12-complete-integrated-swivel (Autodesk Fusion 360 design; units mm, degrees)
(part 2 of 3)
sketch "B Facet 180 Triangle 3" plane through (0, -75, 0) normal (0, -1, 0) x axis (-1, 0, 0)
  line L1 (60.9665, 27.066) -> (-2.067, -27.066)
  line L2 (124, -27.066) -> (60.9665, 27.066)
  line L3 (-2.067, -27.066) -> (124, -27.066)
  line L4 (60.9665, 21.7934) -> (8.7304, -23.066)
  line L5 (113.2026, -23.066) -> (60.9665, 21.7934)
  line L6 (8.7304, -23.066) -> (113.2026, -23.066)
  point P1 (0, 0)
  point P2 (-2.067, -27.066)
  point P3 (60.9665, 27.066)
  point P4 (124, -27.066)
  dimension "d477" distance P1 P2 = 2.067 (= "Linear Dimension-2")
  dimension "d478" distance P1 P2 = 27.066 (= "Linear Dimension-3")
  dimension "d479" distance P1 P3 = 60.9665 (= "Linear Dimension-4")
  dimension "d480" distance P1 P3 = 27.066 (= "Linear Dimension-5")
  dimension "d481" distance P1 P4 = 124 (= "Linear Dimension-6")
  dimension "d482" distance P1 P4 = 27.066 (= "Linear Dimension-7")
  dimension "d483" = 4 (= "memberWidth / 2")
extrude "Extrude14" cut sketch "B Facet 180 Triangle 3" profile of L5 L6 L4 against normal blind 4.7 (magnitude of "-( wall + 0.2 mm )")
sketch "B Facet 180 Triangle 4" plane through (0, -75, 0) normal (0, -1, 0) x axis (-1, 0, 0)
  line L1 (124, -27.066) -> (60.9665, 27.066)
  line L2 (124, 27.066) -> (124, -27.066)
  line L3 (60.9665, 27.066) -> (124, 27.066)
  line L4 (120, -18.3583) -> (71.7639, 23.066)
  line L5 (120, 23.066) -> (120, -18.3583)
  line L6 (71.7639, 23.066) -> (120, 23.066)
  point P1 (0, 0)
  point P2 (60.9665, 27.066)
  point P3 (124, -27.066)
  point P4 (124, 27.066)
  dimension "d486" distance P1 P2 = 60.9665 (= "Linear Dimension-2")
  dimension "d487" distance P1 P2 = 27.066 (= "Linear Dimension-3")
  dimension "d488" distance P1 P3 = 124 (= "Linear Dimension-4")
  dimension "d489" distance P1 P3 = 27.066 (= "Linear Dimension-5")
  dimension "d490" distance P1 P4 = 124 (= "Linear Dimension-6")
  dimension "d491" distance P1 P4 = 27.066 (= "Linear Dimension-7")
  dimension "d492" = -4 (= "-memberWidth / 2")
extrude "Extrude15" cut sketch "B Facet 180 Triangle 4" profile of L5 L6 L4 against normal blind 4.7 (magnitude of "-( wall + 0.2 mm )")
fillet "Fillet5" radius 1.5 (= "apertureRadius")
work_plane "WorkPlane11" RotateAngle 135 ExtraOffset 0
work_plane "WorkPlane12" AlongDistance 75 (= "bodyWidth / 2") ExtraOffset 0
sketch "B Facet 225 Triangle 1" plane through (0, -53.033, -53.033) normal (0, -0.7071, -0.7071) x axis (1, 0, 0)
  line L1 (23.9949, -27.066) -> (62.2721, 27.066)
  line L2 (0.1814, 27.066) -> (23.9949, -27.066)
  line L3 (62.2721, 27.066) -> (0.1814, 27.066)
  line L4 (24.81, -18.9852) -> (54.5447, 23.066)
  line L5 (6.311, 23.066) -> (24.81, -18.9852)
  line L6 (54.5447, 23.066) -> (6.311, 23.066)
  point P1 (0, 0)
  point P2 (62.2721, 27.066)
  point P3 (23.9949, -27.066)
  point P4 (0.1814, 27.066)
  dimension "d501" distance P1 P2 = 62.2721 (= "Linear Dimension-2")
  dimension "d502" distance P1 P2 = 27.066 (= "Linear Dimension-3")
  dimension "d503" distance P1 P3 = 23.9949 (= "Linear Dimension-4")
  dimension "d504" distance P1 P3 = 27.066 (= "Linear Dimension-5")
  dimension "d505" distance P1 P4 = 0.1814 (= "Linear Dimension-6")
  dimension "d506" distance P1 P4 = 27.066 (= "Linear Dimension-7")
  dimension "d507" = 4 (= "memberWidth / 2")
extrude "Extrude16" cut sketch "B Facet 225 Triangle 1" profile of L5 L6 L4 against normal blind 4.7 (magnitude of "-( wall + 0.2 mm )")
sketch "B Facet 225 Triangle 2" plane through (0, -53.033, -53.033) normal (0, -0.7071, -0.7071) x axis (1, 0, 0)
  line L1 (0.1814, 27.066) -> (23.9949, -27.066)
  line L2 (-74.6684, -27.066) -> (0.1814, 27.066)
  line L3 (23.9949, -27.066) -> (-74.6684, -27.066)
  line L4 (-1.4863, 20.9235) -> (17.8653, -23.066)
  line L5 (-62.3117, -23.066) -> (-1.4863, 20.9235)
  line L6 (17.8653, -23.066) -> (-62.3117, -23.066)
  point P1 (0, 0)
  point P2 (23.9949, -27.066)
  point P3 (0.1814, 27.066)
  point P4 (-74.6684, -27.066)
  dimension "d510" distance P1 P2 = 23.9949 (= "Linear Dimension-2")
  dimension "d511" distance P1 P2 = 27.066 (= "Linear Dimension-3")
  dimension "d512" distance P1 P3 = 0.1814 (= "Linear Dimension-4")
  dimension "d513" distance P1 P3 = 27.066 (= "Linear Dimension-5")
  dimension "d514" distance P1 P4 = 74.6684 (= "Linear Dimension-6")
  dimension "d515" distance P1 P4 = 27.066 (= "Linear Dimension-7")
  dimension "d516" = -4 (= "-memberWidth / 2")
extrude "Extrude17" cut sketch "B Facet 225 Triangle 2" profile of L5 L6 L4 against normal blind 4.7 (magnitude of "-( wall + 0.2 mm )")
sketch "B Facet 225 Triangle 3" plane through (0, -53.033, -53.033) normal (0, -0.7071, -0.7071) x axis (1, 0, 0)
  line L1 (-74.6684, -27.066) -> (0.1814, 27.066)
  line L2 (-124, 27.066) -> (-74.6684, -27.066)
  line L3 (0.1814, 27.066) -> (-124, 27.066)
  line L4 (-74.1179, -21.7315) -> (-12.1753, 23.066)
  line L5 (-114.9429, 23.066) -> (-74.1179, -21.7315)
  line L6 (-12.1753, 23.066) -> (-114.9429, 23.066)
  point P1 (0, 0)
  point P2 (0.1814, 27.066)
  point P3 (-74.6684, -27.066)
  point P4 (-124, 27.066)
  dimension "d519" distance P1 P2 = 0.1814 (= "Linear Dimension-2")
  dimension "d520" distance P1 P2 = 27.066 (= "Linear Dimension-3")
  dimension "d521" distance P1 P3 = 74.6684 (= "Linear Dimension-4")
  dimension "d522" distance P1 P3 = 27.066 (= "Linear Dimension-5")
  dimension "d523" distance P1 P4 = 124 (= "Linear Dimension-6")
  dimension "d524" distance P1 P4 = 27.066 (= "Linear Dimension-7")
  dimension "d525" = 4 (= "memberWidth / 2")
extrude "Extrude18" cut sketch "B Facet 225 Triangle 3" profile of L5 L6 L4 against normal blind 4.7 (magnitude of "-( wall + 0.2 mm )")
sketch "B Facet 225 Triangle 4" plane through (0, -53.033, -53.033) normal (0, -0.7071, -0.7071) x axis (1, 0, 0)
  line L1 (-124, 27.066) -> (-74.6684, -27.066)
  line L2 (-124, -27.066) -> (-124, 27.066)
  line L3 (-74.6684, -27.066) -> (-124, -27.066)
  line L4 (-120, 16.7383) -> (-83.7255, -23.066)
  line L5 (-120, -23.066) -> (-120, 16.7383)
  line L6 (-83.7255, -23.066) -> (-120, -23.066)
  point P1 (0, 0)
  point P2 (-74.6684, -27.066)
  point P3 (-124, 27.066)
  point P4 (-124, -27.066)
  dimension "d528" distance P1 P2 = 74.6684 (= "Linear Dimension-2")
  dimension "d529" distance P1 P2 = 27.066 (= "Linear Dimension-3")
  dimension "d530" distance P1 P3 = 124 (= "Linear Dimension-4")
  dimension "d531" distance P1 P3 = 27.066 (= "Linear Dimension-5")
  dimension "d532" distance P1 P4 = 124 (= "Linear Dimension-6")
  dimension "d533" distance P1 P4 = 27.066 (= "Linear Dimension-7")
  dimension "d534" = -4 (= "-memberWidth / 2")
extrude "Extrude19" cut sketch "B Facet 225 Triangle 4" profile of L5 L6 L4 against normal blind 4.7 (magnitude of "-( wall + 0.2 mm )")
fillet "Fillet6" radius 1.5 (= "apertureRadius")
work_plane "WorkPlane13" RotateAngle 180 ExtraOffset 0
work_plane "WorkPlane14" AlongDistance 75 (= "bodyWidth / 2") ExtraOffset 0
sketch "B Facet 270 Triangle 1" plane through (0, 0, -75) normal (0, 0, -1) x axis (-1, 0, 0)
  line L1 (36.9655, 27.066) -> (-17.1665, -27.066)
  line L2 (53.4167, -27.066) -> (36.9655, 27.066)
  line L3 (-17.1665, -27.066) -> (53.4167, -27.066)
  line L4 (35.0777, 19.5214) -> (-7.5097, -23.066)
  line L5 (48.0205, -23.066) -> (35.0777, 19.5214)
  line L6 (-7.5097, -23.066) -> (48.0205, -23.066)
  point P1 (0, 0)
  point P2 (-17.1665, -27.066)
  point P3 (36.9655, 27.066)
  point P4 (53.4167, -27.066)
  dimension "d543" distance P1 P2 = 17.1665 (= "Linear Dimension-2")
  dimension "d544" distance P1 P2 = 27.066 (= "Linear Dimension-3")
  dimension "d545" distance P1 P3 = 36.9655 (= "Linear Dimension-4")
  dimension "d546" distance P1 P3 = 27.066 (= "Linear Dimension-5")
  dimension "d547" distance P1 P4 = 53.4167 (= "Linear Dimension-6")
  dimension "d548" distance P1 P4 = 27.066 (= "Linear Dimension-7")
  dimension "d549" = 4 (= "memberWidth / 2")
extrude "Extrude20" cut sketch "B Facet 270 Triangle 1" profile of L5 L6 L4 against normal blind 4.7 (magnitude of "-( wall + 0.2 mm )")
sketch "B Facet 270 Triangle 2" plane through (0, 0, -75) normal (0, 0, -1) x axis (-1, 0, 0)
  line L1 (53.4167, -27.066) -> (36.9655, 27.066)
  line L2 (124, 27.066) -> (53.4167, -27.066)
  line L3 (36.9655, 27.066) -> (124, 27.066)
  line L4 (55.5648, -20.3777) -> (42.3618, 23.066)
  line L5 (112.2115, 23.066) -> (55.5648, -20.3777)
  line L6 (42.3618, 23.066) -> (112.2115, 23.066)
  point P1 (0, 0)
  point P2 (36.9655, 27.066)
  point P3 (53.4167, -27.066)
  point P4 (124, 27.066)
  dimension "d552" distance P1 P2 = 36.9655 (= "Linear Dimension-2")
  dimension "d553" distance P1 P2 = 27.066 (= "Linear Dimension-3")
  dimension "d554" distance P1 P3 = 53.4167 (= "Linear Dimension-4")
  dimension "d555" distance P1 P3 = 27.066 (= "Linear Dimension-5")
  dimension "d556" distance P1 P4 = 124 (= "Linear Dimension-6")
  dimension "d557" distance P1 P4 = 27.066 (= "Linear Dimension-7")
  dimension "d558" = -4 (= "-memberWidth / 2")
extrude "Extrude21" cut sketch "B Facet 270 Triangle 2" profile of L5 L6 L4 against normal blind 4.7 (magnitude of "-( wall + 0.2 mm )")
sketch "B Facet 270 Triangle 3" plane through (0, 0, -75) normal (0, 0, -1) x axis (-1, 0, 0)
  line L1 (124, 27.066) -> (53.4167, -27.066)
  line L2 (124, -27.066) -> (124, 27.066)
  line L3 (53.4167, -27.066) -> (124, -27.066)
  line L4 (120, 18.9574) -> (65.2053, -23.066)
  line L5 (120, -23.066) -> (120, 18.9574)
  line L6 (65.2053, -23.066) -> (120, -23.066)
  point P1 (0, 0)
  point P2 (53.4167, -27.066)
  point P3 (124, 27.066)
  point P4 (124, -27.066)
  dimension "d561" distance P1 P2 = 53.4167 (= "Linear Dimension-2")
  dimension "d562" distance P1 P2 = 27.066 (= "Linear Dimension-3")
  dimension "d563" distance P1 P3 = 124 (= "Linear Dimension-4")
  dimension "d564" distance P1 P3 = 27.066 (= "Linear Dimension-5")
  dimension "d565" distance P1 P4 = 124 (= "Linear Dimension-6")
  dimension "d566" distance P1 P4 = 27.066 (= "Linear Dimension-7")
  dimension "d567" = 4 (= "memberWidth / 2")
extrude "Extrude22" cut sketch "B Facet 270 Triangle 3" profile of L5 L6 L4 against normal blind 4.7 (magnitude of "-( wall + 0.2 mm )")
fillet "Fillet7" radius 1.5 (= "apertureRadius")
work_plane "WorkPlane15" RotateAngle 225 ExtraOffset 0
work_plane "WorkPlane16" AlongDistance 75 (= "bodyWidth / 2") ExtraOffset 0
sketch "B Facet 315 Triangle 1" plane through (0, 53.033, -53.033) normal (0, 0.7071, -0.7071) x axis (1, 0, 0)
  line L1 (-82.0711, -27.066) -> (-43.7939, 27.066)
  line L2 (-124, 27.066) -> (-82.0711, -27.066)
  line L3 (-43.7939, 27.066) -> (-124, 27.066)
  line L4 (-82.2175, -20.3449) -> (-51.5213, 23.066)
  line L5 (-115.8422, 23.066) -> (-82.2175, -20.3449)
  line L6 (-51.5213, 23.066) -> (-115.8422, 23.066)
  point P1 (0, 0)
  point P2 (-43.7939, 27.066)
  point P3 (-82.0711, -27.066)
  point P4 (-124, 27.066)
  dimension "d576" distance P1 P2 = 43.7939 (= "Linear Dimension-2")
  dimension "d577" distance P1 P2 = 27.066 (= "Linear Dimension-3")
  dimension "d578" distance P1 P3 = 82.0711 (= "Linear Dimension-4")
  dimension "d579" distance P1 P3 = 27.066 (= "Linear Dimension-5")
  dimension "d580" distance P1 P4 = 124 (= "Linear Dimension-6")
  dimension "d581" distance P1 P4 = 27.066 (= "Linear Dimension-7")
  dimension "d582" = 4 (= "memberWidth / 2")
extrude "Extrude23" cut sketch "B Facet 315 Triangle 1" profile of L5 L6 L4 against normal blind 4.7 (magnitude of "-( wall + 0.2 mm )")
sketch "B Facet 315 Triangle 2" plane through (0, 53.033, -53.033) normal (0, 0.7071, -0.7071) x axis (1, 0, 0)
  line L1 (-124, 27.066) -> (-82.0711, -27.066)
  line L2 (-124, -27.066) -> (-124, 27.066)
  line L3 (-82.0711, -27.066) -> (-124, -27.066)
  line L4 (-120, 15.3697) -> (-90.2289, -23.066)
  line L5 (-120, -23.066) -> (-120, 15.3697)
  line L6 (-90.2289, -23.066) -> (-120, -23.066)
  point P1 (0, 0)
  point P2 (-82.0711, -27.066)
  point P3 (-124, 27.066)
  point P4 (-124, -27.066)
  dimension "d585" distance P1 P2 = 82.0711 (= "Linear Dimension-2")
  dimension "d586" distance P1 P2 = 27.066 (= "Linear Dimension-3")
  dimension "d587" distance P1 P3 = 124 (= "Linear Dimension-4")
  dimension "d588" distance P1 P3 = 27.066 (= "Linear Dimension-5")
  dimension "d589" distance P1 P4 = 124 (= "Linear Dimension-6")
  dimension "d590" distance P1 P4 = 27.066 (= "Linear Dimension-7")
  dimension "d591" = -4 (= "-memberWidth / 2")
extrude "Extrude24" cut sketch "B Facet 315 Triangle 2" profile of L5 L6 L4 against normal blind 4.7 (magnitude of "-( wall + 0.2 mm )")
fillet "Fillet8" radius 1.5 (= "apertureRadius")
work_plane "WorkPlane17" AlongDistance 0.5 (= "qFront") ExtraOffset 0
sketch "A Central Carrier sketch" plane through (0.3536, 0.3536, 0) normal (0.7071, 0.7071, 0) x axis (0, 0, 1)
  circle C1 centre (0, 0) radius 26
  dimension "d598" diameter C1 = 52 (= "carrierOD")
extrude "Extrude25" new body sketch "A Central Carrier sketch" along normal blind 18 (= "spokeDepth")
work_plane "WorkPlane18" AlongDistance 0.5 (= "qFront") ExtraOffset 0
sketch "A Spoke 1 Profile" plane through (0.3536, 0.3536, 0) normal (0.7071, 0.7071, 0) x axis (0, 0, 1)
  line L1 (37.3643, -145.3579) -> (-4.7984, -1.4054)
  line L2 (46.9611, -142.547) -> (37.3643, -145.3579)
  line L3 (4.7984, 1.4054) -> (46.9611, -142.547)
  line L4 (-4.7984, -1.4054) -> (4.7984, 1.4054)
  point P1 (0, 0)
  point P2 (-4.7984, -1.4054)
  point P3 (37.3643, -145.3579)
  point P4 (46.9611, -142.547)
  point P5 (4.7984, 1.4054)
  dimension "d603" distance P1 P2 = 4.7984 (= "Linear Dimension-2")
  dimension "d604" distance P1 P2 = 1.4054 (= "Linear Dimension-3")
  dimension "d605" distance P1 P3 = 37.3643 (= "Linear Dimension-4")
  dimension "d606" distance P1 P3 = 145.3579 (= "Linear Dimension-5")
  dimension "d607" distance P1 P4 = 46.9611 (= "Linear Dimension-6")
  dimension "d608" distance P1 P4 = 142.547 (= "Linear Dimension-7")
  dimension "d609" distance P1 P5 = 4.7984 (= "Linear Dimension-8")
  dimension "d610" distance P1 P5 = 1.4054 (= "Linear Dimension-9")
extrude "Extrude26" add sketch "A Spoke 1 Profile" along normal blind 18 (= "spokeDepth")
sketch "A Spoke 2 Profile" plane through (0.3536, 0.3536, 0) normal (0.7071, 0.7071, 0) x axis (0, 0, 1)
  line L1 (126.9012, -80.1317) -> (-2.5272, -4.3143)
  line L2 (131.9557, -71.5031) -> (126.9012, -80.1317)
  line L3 (2.5272, 4.3143) -> (131.9557, -71.5031)
  line L4 (-2.5272, -4.3143) -> (2.5272, 4.3143)
  point P1 (0, 0)
  point P2 (-2.5272, -4.3143)
  point P3 (126.9012, -80.1317)
  point P4 (131.9557, -71.5031)
  point P5 (2.5272, 4.3143)
  dimension "d613" distance P1 P2 = 2.5272 (= "Linear Dimension-2")
  dimension "d614" distance P1 P2 = 4.3143 (= "Linear Dimension-3")
  dimension "d615" distance P1 P3 = 126.9012 (= "Linear Dimension-4")
  dimension "d616" distance P1 P3 = 80.1317 (= "Linear Dimension-5")
  dimension "d617" distance P1 P4 = 131.9557 (= "Linear Dimension-6")
  dimension "d618" distance P1 P4 = 71.5031 (= "Linear Dimension-7")
  dimension "d619" distance P1 P5 = 2.5272 (= "Linear Dimension-8")
  dimension "d620" distance P1 P5 = 4.3143 (= "Linear Dimension-9")
extrude "Extrude27" add sketch "A Spoke 2 Profile" along normal blind 18 (= "spokeDepth")
sketch "A Spoke 3 Profile" plane through (0.3536, 0.3536, 0) normal (0.7071, 0.7071, 0) x axis (0, 0, 1)
  line L1 (131.9557, 71.5031) -> (2.5272, -4.3143)
  line L2 (126.9012, 80.1317) -> (131.9557, 71.5031)
  line L3 (-2.5272, 4.3143) -> (126.9012, 80.1317)
  line L4 (2.5272, -4.3143) -> (-2.5272, 4.3143)
  point P1 (0, 0)
  point P2 (2.5272, -4.3143)
  point P3 (131.9557, 71.5031)
  point P4 (126.9012, 80.1317)
  point P5 (-2.5272, 4.3143)
  dimension "d623" distance P1 P2 = 2.5272 (= "Linear Dimension-2")
  dimension "d624" distance P1 P2 = 4.3143 (= "Linear Dimension-3")
  dimension "d625" distance P1 P3 = 131.9557 (= "Linear Dimension-4")
  dimension "d626" distance P1 P3 = 71.5031 (= "Linear Dimension-5")
  dimension "d627" distance P1 P4 = 126.9012 (= "Linear Dimension-6")
  dimension "d628" distance P1 P4 = 80.1317 (= "Linear Dimension-7")
  dimension "d629" distance P1 P5 = 2.5272 (= "Linear Dimension-8")
  dimension "d630" distance P1 P5 = 4.3143 (= "Linear Dimension-9")
extrude "Extrude28" add sketch "A Spoke 3 Profile" along normal blind 18 (= "spokeDepth")
sketch "A Spoke 4 Profile" plane through (0.3536, 0.3536, 0) normal (0.7071, 0.7071, 0) x axis (0, 0, 1)
  line L1 (46.9611, 142.547) -> (4.7984, -1.4054)
  line L2 (37.3643, 145.3579) -> (46.9611, 142.547)
  line L3 (-4.7984, 1.4054) -> (37.3643, 145.3579)
  line L4 (4.7984, -1.4054) -> (-4.7984, 1.4054)
  point P1 (0, 0)
  point P2 (4.7984, -1.4054)
  point P3 (46.9611, 142.547)
  point P4 (37.3643, 145.3579)
  point P5 (-4.7984, 1.4054)
  dimension "d633" distance P1 P2 = 4.7984 (= "Linear Dimension-2")
  dimension "d634" distance P1 P2 = 1.4054 (= "Linear Dimension-3")
  dimension "d635" distance P1 P3 = 46.9611 (= "Linear Dimension-4")
  dimension "d636" distance P1 P3 = 142.547 (= "Linear Dimension-5")
  dimension "d637" distance P1 P4 = 37.3643 (= "Linear Dimension-6")
  dimension "d638" distance P1 P4 = 145.3579 (= "Linear Dimension-7")
  dimension "d639" distance P1 P5 = 4.7984 (= "Linear Dimension-8")
  dimension "d640" distance P1 P5 = 1.4054 (= "Linear Dimension-9")
extrude "Extrude29" add sketch "A Spoke 4 Profile" along normal blind 18 (= "spokeDepth")
sketch "A Spoke 5 Profile" plane through (0.3536, 0.3536, 0) normal (0.7071, 0.7071, 0) x axis (0, 0, 1)
  line L1 (-37.3643, 145.3579) -> (4.7984, 1.4054)
  line L2 (-46.9611, 142.547) -> (-37.3643, 145.3579)
  line L3 (-4.7984, -1.4054) -> (-46.9611, 142.547)
  line L4 (4.7984, 1.4054) -> (-4.7984, -1.4054)
  point P1 (0, 0)
  point P2 (4.7984, 1.4054)
  point P3 (-37.3643, 145.3579)
  point P4 (-46.9611, 142.547)
  point P5 (-4.7984, -1.4054)
  dimension "d643" distance P1 P2 = 4.7984 (= "Linear Dimension-2")
  dimension "d644" distance P1 P2 = 1.4054 (= "Linear Dimension-3")
  dimension "d645" distance P1 P3 = 37.3643 (= "Linear Dimension-4")
  dimension "d646" distance P1 P3 = 145.3579 (= "Linear Dimension-5")
  dimension "d647" distance P1 P4 = 46.9611 (= "Linear Dimension-6")
  dimension "d648" distance P1 P4 = 142.547 (= "Linear Dimension-7")
  dimension "d649" distance P1 P5 = 4.7984 (= "Linear Dimension-8")
  dimension "d650" distance P1 P5 = 1.4054 (= "Linear Dimension-9")
extrude "Extrude30" add sketch "A Spoke 5 Profile" along normal blind 18 (= "spokeDepth")
sketch "A Spoke 6 Profile" plane through (0.3536, 0.3536, 0) normal (0.7071, 0.7071, 0) x axis (0, 0, 1)
  line L1 (-126.9012, 80.1317) -> (2.5272, 4.3143)
  line L2 (-131.9557, 71.5031) -> (-126.9012, 80.1317)
  line L3 (-2.5272, -4.3143) -> (-131.9557, 71.5031)
  line L4 (2.5272, 4.3143) -> (-2.5272, -4.3143)
  point P1 (0, 0)
  point P2 (2.5272, 4.3143)
  point P3 (-126.9012, 80.1317)
  point P4 (-131.9557, 71.5031)
  point P5 (-2.5272, -4.3143)
  dimension "d653" distance P1 P2 = 2.5272 (= "Linear Dimension-2")
  dimension "d654" distance P1 P2 = 4.3143 (= "Linear Dimension-3")
  dimension "d655" distance P1 P3 = 126.9012 (= "Linear Dimension-4")
  dimension "d656" distance P1 P3 = 80.1317 (= "Linear Dimension-5")
  dimension "d657" distance P1 P4 = 131.9557 (= "Linear Dimension-6")
  dimension "d658" distance P1 P4 = 71.5031 (= "Linear Dimension-7")
  dimension "d659" distance P1 P5 = 2.5272 (= "Linear Dimension-8")
  dimension "d660" distance P1 P5 = 4.3143 (= "Linear Dimension-9")
extrude "Extrude31" add sketch "A Spoke 6 Profile" along normal blind 18 (= "spokeDepth")
sketch "A Spoke 7 Profile" plane through (0.3536, 0.3536, 0) normal (0.7071, 0.7071, 0) x axis (0, 0, 1)
  line L1 (-131.9557, -71.5031) -> (-2.5272, 4.3143)
  line L2 (-126.9012, -80.1317) -> (-131.9557, -71.5031)
  line L3 (2.5272, -4.3143) -> (-126.9012, -80.1317)
  line L4 (-2.5272, 4.3143) -> (2.5272, -4.3143)
  point P1 (0, 0)
  point P2 (-2.5272, 4.3143)
  point P3 (-131.9557, -71.5031)
  point P4 (-126.9012, -80.1317)
  point P5 (2.5272, -4.3143)
  dimension "d663" distance P1 P2 = 2.5272 (= "Linear Dimension-2")
  dimension "d664" distance P1 P2 = 4.3143 (= "Linear Dimension-3")
  dimension "d665" distance P1 P3 = 131.9557 (= "Linear Dimension-4")
  dimension "d666" distance P1 P3 = 71.5031 (= "Linear Dimension-5")
  dimension "d667" distance P1 P4 = 126.9012 (= "Linear Dimension-6")
  dimension "d668" distance P1 P4 = 80.1317 (= "Linear Dimension-7")
  dimension "d669" distance P1 P5 = 2.5272 (= "Linear Dimension-8")
  dimension "d670" distance P1 P5 = 4.3143 (= "Linear Dimension-9")
extrude "Extrude32" add sketch "A Spoke 7 Profile" along normal blind 18 (= "spokeDepth")
sketch "A Spoke 8 Profile" plane through (0.3536, 0.3536, 0) normal (0.7071, 0.7071, 0) x axis (0, 0, 1)
  line L1 (-46.9611, -142.547) -> (-4.7984, 1.4054)
  line L2 (-37.3643, -145.3579) -> (-46.9611, -142.547)
  line L3 (4.7984, 1.4054) -> (-37.3643, -145.3579)
  line L4 (-4.7984, 1.4054) -> (4.7984, 1.4054)
  point P1 (0, 0)
  point P2 (-4.7984, 1.4054)
  point P3 (-46.9611, -142.547)
  point P4 (-37.3643, -145.3579)
  point P5 (4.7984, 1.4054)
  dimension "d673" distance P1 P2 = 4.7984 (= "Linear Dimension-2")
  dimension "d674" distance P1 P2 = 1.4054 (= "Linear Dimension-3")
  dimension "d675" distance P1 P3 = 46.9611 (= "Linear Dimension-4")
  dimension "d676" distance P1 P3 = 142.547 (= "Linear Dimension-5")
  dimension "d677" distance P1 P4 = 37.3643 (= "Linear Dimension-6")
  dimension "d678" distance P1 P4 = 145.3579 (= "Linear Dimension-7")
  dimension "d679" distance P1 P5 = 4.7984 (= "Linear Dimension-8")
  dimension "d680" distance P1 P5 = 1.4054 (= "Linear Dimension-9")
extrude "Extrude33" add sketch "A Spoke 8 Profile" along normal blind 18 (= "spokeDepth")
sketch "Spoke Outer Envelope" plane through (0, 0, 0) normal (1, 0, 0) x axis (0, 0, -1)
  line L1 (31.066, 75) -> (75, 31.066)
  line L2 (-31.066, 75) -> (31.066, 75)
  line L3 (-75, 31.066) -> (-31.066, 75)
  line L4 (-75, -31.066) -> (-75, 31.066)
  line L5 (-31.066, -75) -> (-75, -31.066)
  line L6 (31.066, -75) -> (-31.066, -75)
  line L7 (75, -31.066) -> (31.066, -75)
  line L8 (75, 31.066) -> (75, -31.066)
  point P1 (0, 0)
  point P10 (0, 0)
  point P3 (31.066, 75)
  point P8 (31.066, -75)
  coincident P1 P10
  horizontal L2
  dimension "d683" distance P3 P8 = 150 (= "bodyWidth")
extrude "Extrude34" sketch "Spoke Outer Envelope" distance 260 (= "bodyLength")
fillet "Fillet9" radius 1 (= "rootRadius")
work_plane "WorkPlane19" AlongDistance 10.6 (= "qFrontBack") ExtraOffset 0
sketch "A Rear Carrier Clearance sketch" plane through (7.4953, 7.4953, 0) normal (0.7071, 0.7071, 0) x axis (0, 0, 1)
  circle C1 centre (0, 0) radius 23
  dimension "d690" diameter C1 = 46 (= "rearCarrierClearance")
extrude "Extrude35" cut sketch "A Rear Carrier Clearance sketch" along normal blind 18 (= "spokeDepth")
work_plane "WorkPlane20" AlongDistance 0.5 (= "qFront") ExtraOffset 0
sketch "A Seal Relief sketch" plane through (0.3536, 0.3536, 0) normal (0.7071, 0.7071, 0) x axis (0, 0, 1)
  circle C1 centre (0, 0) radius 9.75
  dimension "d695" diameter C1 = 19.5 (= "raceRelief")
extrude "Extrude36" cut sketch "A Seal Relief sketch" along normal blind 10.1 (= "frontSeatDepth + shoulder")
work_plane "WorkPlane21" AlongDistance 0.5 (= "qFront") ExtraOffset 0
sketch "A Front Bearing Seat sketch" plane through (0.3536, 0.3536, 0) normal (0.7071, 0.7071, 0) x axis (0, 0, 1)
  circle C1 centre (0, 0) radius 11.1
  dimension "d700" diameter C1 = 22.2 (= "seatDiameter")
extrude "Extrude37" cut sketch "A Front Bearing Seat sketch" along normal blind 7.1 (= "frontSeatDepth")
work_plane "WorkPlane22" AlongDistance 0.5 (= "qFront") ExtraOffset 0
sketch "A Support Bolt seed" plane through (0.3536, 0.3536, 0) normal (0.7071, 0.7071, 0) x axis (0, 0, 1)
  line L1 (17, 0) -> (0, 0)
  circle C1 centre (17, 0) radius 1.65
  point P1 (0, 0)
  point P2 (17, 0)
  horizontal L1
  dimension "d705" distance P1 P2 = 17 (= "supportCircle / 2")
  dimension "d706" diameter C1 = 3.3 (= "m3Clearance")
extrude "Extrude38" cut sketch "A Support Bolt seed" profile of C1 along normal blind 10.1 (= "frontSeatDepth + shoulder")
circular_pattern "C-Pattern1" TotalAngle 360
work_plane "WorkPlane23" AlongDistance 0.5 (= "qFront") ExtraOffset 0
sketch "A Front Bearing Boss sketch" plane through (0.3536, 0.3536, 0) normal (0.7071, 0.7071, 0) x axis (0, 0, 1)
  circle C1 centre (0, 0) radius 22
  dimension "d713" diameter C1 = 44 (= "coreOD")
chamfer "Chamfer1" distance 0.4 (= "entryChamfer")
work_plane "WorkPlane24" AlongDistance 75 (= "bodyWidth / 2") ExtraOffset 0
sketch "A Collar Driver Corridors" plane through (0, 0, 75) normal (0, 0, 1) x axis (1, 0, 0)
  circle C1 centre (6.7175, 15.9099) radius 3
  circle C2 centre (15.9099, 6.7175) radius 3
  point P1 (0, 0)
  point P2 (6.7175, 15.9099)
  point P3 (15.9099, 6.7175)
  dimension "d717" distance P1 P2 = 6.7175 (= "abs(( 16 mm + ( -6.5 mm ) ) / sqrt(2))")
  dimension "d718" distance P1 P2 = 15.9099 (= "abs(( 16 mm - ( -6.5 mm ) ) / sqrt(2))")
  dimension "d719" diameter C1 = 6
  dimension "d720" distance P1 P3 = 15.9099 (= "abs(( 16 mm + ( 6.5 mm ) ) / sqrt(2))")
  dimension "d721" distance P1 P3 = 6.7175 (= "abs(( 16 mm - ( 6.5 mm ) ) / sqrt(2))")
  dimension "d722" diameter C2 = 6
extrude "Extrude39" cut sketch "A Collar Driver Corridors" against normal blind 75 (magnitude of "-( bodyWidth / 2 )")
work_plane "WorkPlane17" ExtraOffset 0
sketch "B Central Carrier sketch" plane through (-0.3536, -0.3536, 0) normal (0.7071, 0.7071, 0) x axis (0, 0, 1)
  circle C1 centre (0, 0) radius 38
  dimension "d727" diameter C1 = 76 (= "mountOD")
extrude "Extrude25" new body sketch "B Central Carrier sketch" no distance stored
work_plane "WorkPlane18" ExtraOffset 0
sketch "B Spoke 1 Profile" plane through (-0.3536, -0.3536, 0) normal (0.7071, 0.7071, 0) x axis (0, 0, 1)
  line L1 (37.3643, -145.3579) -> (-4.7984, -1.4054)
  line L2 (46.9611, -142.547) -> (37.3643, -145.3579)
  line L3 (4.7984, 1.4054) -> (46.9611, -142.547)
  line L4 (-4.7984, -1.4054) -> (4.7984, 1.4054)
  point P1 (0, 0)
  point P2 (-4.7984, -1.4054)
  point P3 (37.3643, -145.3579)
  point P4 (46.9611, -142.547)
  point P5 (4.7984, 1.4054)
  dimension "d732" distance P1 P2 = 4.7984 (= "Linear Dimension-2")
  dimension "d733" distance P1 P2 = 1.4054 (= "Linear Dimension-3")
  dimension "d734" distance P1 P3 = 37.3643 (= "Linear Dimension-4")
  dimension "d735" distance P1 P3 = 145.3579 (= "Linear Dimension-5")
  dimension "d736" distance P1 P4 = 46.9611 (= "Linear Dimension-6")
  dimension "d737" distance P1 P4 = 142.547 (= "Linear Dimension-7")
  dimension "d738" distance P1 P5 = 4.7984 (= "Linear Dimension-8")
  dimension "d739" distance P1 P5 = 1.4054 (= "Linear Dimension-9")
extrude "Extrude26" add sketch "B Spoke 1 Profile" no distance stored
sketch "B Spoke 2 Profile" plane through (-0.3536, -0.3536, 0) normal (0.7071, 0.7071, 0) x axis (0, 0, 1)
  line L1 (126.9012, -80.1317) -> (-2.5272, -4.3143)
  line L2 (131.9557, -71.5031) -> (126.9012, -80.1317)
  line L3 (2.5272, 4.3143) -> (131.9557, -71.5031)
  line L4 (-2.5272, -4.3143) -> (2.5272, 4.3143)
  point P1 (0, 0)
  point P2 (-2.5272, -4.3143)
  point P3 (126.9012, -80.1317)
  point P4 (131.9557, -71.5031)
  point P5 (2.5272, 4.3143)
  dimension "d742" distance P1 P2 = 2.5272 (= "Linear Dimension-2")
  dimension "d743" distance P1 P2 = 4.3143 (= "Linear Dimension-3")
  dimension "d744" distance P1 P3 = 126.9012 (= "Linear Dimension-4")
  dimension "d745" distance P1 P3 = 80.1317 (= "Linear Dimension-5")
  dimension "d746" distance P1 P4 = 131.9557 (= "Linear Dimension-6")
  dimension "d747" distance P1 P4 = 71.5031 (= "Linear Dimension-7")
  dimension "d748" distance P1 P5 = 2.5272 (= "Linear Dimension-8")
  dimension "d749" distance P1 P5 = 4.3143 (= "Linear Dimension-9")
extrude "Extrude27" add sketch "B Spoke 2 Profile" no distance stored
sketch "B Spoke 3 Profile" plane through (-0.3536, -0.3536, 0) normal (0.7071, 0.7071, 0) x axis (0, 0, 1)
  line L1 (131.9557, 71.5031) -> (2.5272, -4.3143)
  line L2 (126.9012, 80.1317) -> (131.9557, 71.5031)
  line L3 (-2.5272, 4.3143) -> (126.9012, 80.1317)
  line L4 (2.5272, -4.3143) -> (-2.5272, 4.3143)
  point P1 (0, 0)
  point P2 (2.5272, -4.3143)
  point P3 (131.9557, 71.5031)
  point P4 (126.9012, 80.1317)
  point P5 (-2.5272, 4.3143)
  dimension "d752" distance P1 P2 = 2.5272 (= "Linear Dimension-2")
  dimension "d753" distance P1 P2 = 4.3143 (= "Linear Dimension-3")
  dimension "d754" distance P1 P3 = 131.9557 (= "Linear Dimension-4")
  dimension "d755" distance P1 P3 = 71.5031 (= "Linear Dimension-5")
  dimension "d756" distance P1 P4 = 126.9012 (= "Linear Dimension-6")
  dimension "d757" distance P1 P4 = 80.1317 (= "Linear Dimension-7")
  dimension "d758" distance P1 P5 = 2.5272 (= "Linear Dimension-8")
  dimension "d759" distance P1 P5 = 4.3143 (= "Linear Dimension-9")
extrude "Extrude28" add sketch "B Spoke 3 Profile" no distance stored
sketch "B Spoke 4 Profile" plane through (-0.3536, -0.3536, 0) normal (0.7071, 0.7071, 0) x axis (0, 0, 1)
  line L1 (46.9611, 142.547) -> (4.7984, -1.4054)
  line L2 (37.3643, 145.3579) -> (46.9611, 142.547)
  line L3 (-4.7984, 1.4054) -> (37.3643, 145.3579)
  line L4 (4.7984, -1.4054) -> (-4.7984, 1.4054)
  point P1 (0, 0)
  point P2 (4.7984, -1.4054)
  point P3 (46.9611, 142.547)
  point P4 (37.3643, 145.3579)
  point P5 (-4.7984, 1.4054)
  dimension "d762" distance P1 P2 = 4.7984 (= "Linear Dimension-2")
  dimension "d763" distance P1 P2 = 1.4054 (= "Linear Dimension-3")
  dimension "d764" distance P1 P3 = 46.9611 (= "Linear Dimension-4")
  dimension "d765" distance P1 P3 = 142.547 (= "Linear Dimension-5")
  dimension "d766" distance P1 P4 = 37.3643 (= "Linear Dimension-6")
  dimension "d767" distance P1 P4 = 145.3579 (= "Linear Dimension-7")
  dimension "d768" distance P1 P5 = 4.7984 (= "Linear Dimension-8")
  dimension "d769" distance P1 P5 = 1.4054 (= "Linear Dimension-9")
extrude "Extrude29" add sketch "B Spoke 4 Profile" no distance stored
sketch "B Spoke 5 Profile" plane through (-0.3536, -0.3536, 0) normal (0.7071, 0.7071, 0) x axis (0, 0, 1)
  line L1 (-37.3643, 145.3579) -> (4.7984, 1.4054)
  line L2 (-46.9611, 142.547) -> (-37.3643, 145.3579)
  line L3 (-4.7984, -1.4054) -> (-46.9611, 142.547)
  line L4 (4.7984, 1.4054) -> (-4.7984, -1.4054)
  point P1 (0, 0)
  point P2 (4.7984, 1.4054)
  point P3 (-37.3643, 145.3579)
  point P4 (-46.9611, 142.547)
  point P5 (-4.7984, -1.4054)
  dimension "d772" distance P1 P2 = 4.7984 (= "Linear Dimension-2")
  dimension "d773" distance P1 P2 = 1.4054 (= "Linear Dimension-3")
  dimension "d774" distance P1 P3 = 37.3643 (= "Linear Dimension-4")
  dimension "d775" distance P1 P3 = 145.3579 (= "Linear Dimension-5")
  dimension "d776" distance P1 P4 = 46.9611 (= "Linear Dimension-6")
  dimension "d777" distance P1 P4 = 142.547 (= "Linear Dimension-7")
  dimension "d778" distance P1 P5 = 4.7984 (= "Linear Dimension-8")
  dimension "d779" distance P1 P5 = 1.4054 (= "Linear Dimension-9")
extrude "Extrude30" add sketch "B Spoke 5 Profile" no distance stored
sketch "B Spoke 6 Profile" plane through (-0.3536, -0.3536, 0) normal (0.7071, 0.7071, 0) x axis (0, 0, 1)
  line L1 (-126.9012, 80.1317) -> (2.5272, 4.3143)
  line L2 (-131.9557, 71.5031) -> (-126.9012, 80.1317)
  line L3 (-2.5272, -4.3143) -> (-131.9557, 71.5031)
  line L4 (2.5272, 4.3143) -> (-2.5272, -4.3143)
  point P1 (0, 0)
  point P2 (2.5272, 4.3143)
  point P3 (-126.9012, 80.1317)
  point P4 (-131.9557, 71.5031)
  point P5 (-2.5272, -4.3143)
  dimension "d782" distance P1 P2 = 2.5272 (= "Linear Dimension-2")
  dimension "d783" distance P1 P2 = 4.3143 (= "Linear Dimension-3")
  dimension "d784" distance P1 P3 = 126.9012 (= "Linear Dimension-4")
  dimension "d785" distance P1 P3 = 80.1317 (= "Linear Dimension-5")
  dimension "d786" distance P1 P4 = 131.9557 (= "Linear Dimension-6")
  dimension "d787" distance P1 P4 = 71.5031 (= "Linear Dimension-7")
  dimension "d788" distance P1 P5 = 2.5272 (= "Linear Dimension-8")
  dimension "d789" distance P1 P5 = 4.3143 (= "Linear Dimension-9")
extrude "Extrude31" add sketch "B Spoke 6 Profile" no distance stored
sketch "B Spoke 7 Profile" plane through (-0.3536, -0.3536, 0) normal (0.7071, 0.7071, 0) x axis (0, 0, 1)
  line L1 (-131.9557, -71.5031) -> (-2.5272, 4.3143)
  line L2 (-126.9012, -80.1317) -> (-131.9557, -71.5031)
  line L3 (2.5272, -4.3143) -> (-126.9012, -80.1317)
  line L4 (-2.5272, 4.3143) -> (2.5272, -4.3143)
  point P1 (0, 0)
  point P2 (-2.5272, 4.3143)
  point P3 (-131.9557, -71.5031)
  point P4 (-126.9012, -80.1317)
  point P5 (2.5272, -4.3143)
  dimension "d792" distance P1 P2 = 2.5272 (= "Linear Dimension-2")
  dimension "d793" distance P1 P2 = 4.3143 (= "Linear Dimension-3")
  dimension "d794" distance P1 P3 = 131.9557 (= "Linear Dimension-4")
  dimension "d795" distance P1 P3 = 71.5031 (= "Linear Dimension-5")
  dimension "d796" distance P1 P4 = 126.9012 (= "Linear Dimension-6")
  dimension "d797" distance P1 P4 = 80.1317 (= "Linear Dimension-7")
  dimension "d798" distance P1 P5 = 2.5272 (= "Linear Dimension-8")
  dimension "d799" distance P1 P5 = 4.3143 (= "Linear Dimension-9")
extrude "Extrude32" add sketch "B Spoke 7 Profile" no distance stored
sketch "B Spoke 8 Profile" plane through (-0.3536, -0.3536, 0) normal (0.7071, 0.7071, 0) x axis (0, 0, 1)
  line L1 (-46.9611, -142.547) -> (-4.7984, 1.4054)
  line L2 (-37.3643, -145.3579) -> (-46.9611, -142.547)
  line L3 (4.7984, 1.4054) -> (-37.3643, -145.3579)
  line L4 (-4.7984, 1.4054) -> (4.7984, 1.4054)
  point P1 (0, 0)
  point P2 (-4.7984, 1.4054)
  point P3 (-46.9611, -142.547)
  point P4 (-37.3643, -145.3579)
  point P5 (4.7984, 1.4054)
  dimension "d802" distance P1 P2 = 4.7984 (= "Linear Dimension-2")
  dimension "d803" distance P1 P2 = 1.4054 (= "Linear Dimension-3")
  dimension "d804" distance P1 P3 = 46.9611 (= "Linear Dimension-4")
  dimension "d805" distance P1 P3 = 142.547 (= "Linear Dimension-5")
  dimension "d806" distance P1 P4 = 37.3643 (= "Linear Dimension-6")
  dimension "d807" distance P1 P4 = 145.3579 (= "Linear Dimension-7")
  dimension "d808" distance P1 P5 = 4.7984 (= "Linear Dimension-8")
  dimension "d809" distance P1 P5 = 1.4054 (= "Linear Dimension-9")
extrude "Extrude33" add sketch "B Spoke 8 Profile" no distance stored
sketch "Spoke Outer Envelope" plane through (0, 0, 0) normal (1, 0, 0) x axis (0, 0, -1)
  line L1 (31.066, 75) -> (75, 31.066)
  line L2 (-31.066, 75) -> (31.066, 75)
  line L3 (-75, 31.066) -> (-31.066, 75)
  line L4 (-75, -31.066) -> (-75, 31.066)
  line L5 (-31.066, -75) -> (-75, -31.066)
  line L6 (31.066, -75) -> (-31.066, -75)
  line L7 (75, -31.066) -> (31.066, -75)
  line L8 (75, 31.066) -> (75, -31.066)
  point P1 (0, 0)
  point P10 (0, 0)
  point P3 (31.066, 75)
  point P8 (31.066, -75)
  coincident P1 P10
  horizontal L2
  dimension "d812" distance P3 P8 = 150 (= "bodyWidth")
extrude "Extrude34" sketch "Spoke Outer Envelope" distance 260 (= "bodyLength")
fillet "Fillet9" radius 1 (= "rootRadius")
work_plane "WorkPlane19" ExtraOffset 0
sketch "B Open Hub Cavity sketch" plane through (-0.3536, -0.3536, 0) normal (0.7071, 0.7071, 0) x axis (0, 0, 1)
  circle C1 centre (0, 0) radius 25.15
  dimension "d819" diameter C1 = 50.3 (= "mountOpening")
extrude "Extrude35" cut sketch "B Open Hub Cavity sketch" no distance stored
work_plane "WorkPlane20" ExtraOffset 0
sketch "B Four Mount Holes" plane through (-0.3536, -0.3536, 0) normal (0.7071, 0.7071, 0) x axis (0, 0, 1)
  circle C1 centre (22.6274, 22.6274) radius 2.15
  circle C2 centre (-22.6274, 22.6274) radius 2.15
  circle C3 centre (-22.6274, -22.6274) radius 2.15
  circle C4 centre (22.6274, -22.6274) radius 2.15
  point P1 (0, 0)
  point P2 (22.6274, 22.6274)
  point P3 (-22.6274, 22.6274)
  point P4 (-22.6274, -22.6274)
  point P5 (22.6274, -22.6274)
  dimension "d824" distance P1 P2 = 22.6274 (= "abs(mountCircle / ( 2 * sqrt(2) ))")
  dimension "d825" distance P1 P2 = 22.6274 (= "abs(mountCircle / ( 2 * sqrt(2) ))")
  dimension "d826" diameter C1 = 4.3 (= "m4Clearance")
  dimension "d827" distance P1 P3 = 22.6274 (= "abs(-mountCircle / ( 2 * sqrt(2) ))")
  dimension "d828" distance P1 P3 = 22.6274 (= "abs(mountCircle / ( 2 * sqrt(2) ))")
  dimension "d829" diameter C2 = 4.3 (= "m4Clearance")
  dimension "d830" distance P1 P4 = 22.6274 (= "abs(-mountCircle / ( 2 * sqrt(2) ))")
  dimension "d831" distance P1 P4 = 22.6274 (= "abs(-mountCircle / ( 2 * sqrt(2) ))")
  dimension "d832" diameter C3 = 4.3 (= "m4Clearance")
  dimension "d833" distance P1 P5 = 22.6274 (= "abs(mountCircle / ( 2 * sqrt(2) ))")
  dimension "d834" distance P1 P5 = 22.6274 (= "abs(-mountCircle / ( 2 * sqrt(2) ))")
  dimension "d835" diameter C4 = 4.3 (= "m4Clearance")
extrude "Extrude36" cut sketch "B Four Mount Holes" no distance stored
sketch "B M4 Nut Pocket 1" plane through (-0.3536, -0.3536, 0) normal (0.7071, 0.7071, 0) x axis (0, 0, 1)
  line L1 (24.7059, 26.2274) -> (26.7843, 22.6274)
  line L2 (20.549, 26.2274) -> (24.7059, 26.2274)
  line L3 (18.4705, 22.6274) -> (20.549, 26.2274)
  line L4 (20.549, 19.0274) -> (18.4705, 22.6274)
  line L5 (24.7059, 19.0274) -> (20.549, 19.0274)
  line L6 (26.7843, 22.6274) -> (24.7059, 19.0274)
  circle C1 centre (22.6274, 22.6274) radius 4.1569
  point P3 (26.7843, 22.6274)
  point P4 (24.7059, 26.2274)
  point P5 (20.549, 26.2274)
  point P6 (18.4705, 22.6274)
  point P7 (20.549, 19.0274)
  point P8 (24.7059, 19.0274)
  point P1 (0, 0)
  point P2 (22.6274, 22.6274)
  coincident C1 P3
  coincident C1 P4
  coincident C1 P5
  coincident C1 P6
  coincident C1 P7
  coincident C1 P8
  equal L1 L2
  equal L1 L3
  equal L1 L4
  equal L1 L5
  equal L1 L6
  horizontal L2
  dimension "d838" distance P1 P2 = 22.6274 (= "abs(mountCircle / ( 2 * sqrt(2) ))")
  dimension "d839" distance P1 P2 = 22.6274 (= "abs(mountCircle / ( 2 * sqrt(2) ))")
  dimension "d840" diameter C1 = 8.3138 (= "2 * ( nutAF ) / sqrt(3)")
extrude "Extrude37" cut sketch "B M4 Nut Pocket 1" profile of L1 L2 L3 L4 L5 L6 no distance stored
sketch "B M4 Nut Pocket 2" plane through (-0.3536, -0.3536, 0) normal (0.7071, 0.7071, 0) x axis (0, 0, 1)
  line L1 (-20.549, 26.2274) -> (-18.4705, 22.6274)
  line L2 (-24.7059, 26.2274) -> (-20.549, 26.2274)
  line L3 (-26.7843, 22.6274) -> (-24.7059, 26.2274)
  line L4 (-24.7059, 19.0274) -> (-26.7843, 22.6274)
  line L5 (-20.549, 19.0274) -> (-24.7059, 19.0274)
  line L6 (-18.4705, 22.6274) -> (-20.549, 19.0274)
  circle C1 centre (-22.6274, 22.6274) radius 4.1569
  point P3 (-18.4705, 22.6274)
  point P4 (-20.549, 26.2274)
  point P5 (-24.7059, 26.2274)
  point P6 (-26.7843, 22.6274)
  point P7 (-24.7059, 19.0274)
  point P8 (-20.549, 19.0274)
  point P1 (0, 0)
  point P2 (-22.6274, 22.6274)
  coincident C1 P3
  coincident C1 P4
  coincident C1 P5
  coincident C1 P6
  coincident C1 P7
  coincident C1 P8
  equal L1 L2
  equal L1 L3
  equal L1 L4
  equal L1 L5
  equal L1 L6
  horizontal L2
  dimension "d843" distance P1 P2 = 22.6274 (= "abs(-mountCircle / ( 2 * sqrt(2) ))")
  dimension "d844" distance P1 P2 = 22.6274 (= "abs(mountCircle / ( 2 * sqrt(2) ))")
  dimension "d845" diameter C1 = 8.3138 (= "2 * ( nutAF ) / sqrt(3)")
extrude "Extrude38" cut sketch "B M4 Nut Pocket 2" profile of L1 L2 L3 L4 L5 L6 no distance stored
sketch "B M4 Nut Pocket 3" plane through (-0.3536, -0.3536, 0) normal (0.7071, 0.7071, 0) x axis (0, 0, 1)
  line L1 (-20.549, -19.0274) -> (-18.4705, -22.6274)
  line L2 (-24.7059, -19.0274) -> (-20.549, -19.0274)
  line L3 (-26.7843, -22.6274) -> (-24.7059, -19.0274)
  line L4 (-24.7059, -26.2274) -> (-26.7843, -22.6274)
  line L5 (-20.549, -26.2274) -> (-24.7059, -26.2274)
  line L6 (-18.4705, -22.6274) -> (-20.549, -26.2274)
  circle C1 centre (-22.6274, -22.6274) radius 4.1569
  point P3 (-18.4705, -22.6274)
  point P4 (-20.549, -19.0274)
  point P5 (-24.7059, -19.0274)
  point P6 (-26.7843, -22.6274)
  point P7 (-24.7059, -26.2274)
  point P8 (-20.549, -26.2274)
  point P1 (0, 0)
  point P2 (-22.6274, -22.6274)
  coincident C1 P3
  coincident C1 P4
  coincident C1 P5
  coincident C1 P6
  coincident C1 P7
  coincident C1 P8
  equal L1 L2
  equal L1 L3
  equal L1 L4
  equal L1 L5
  equal L1 L6
  horizontal L2
  dimension "d848" distance P1 P2 = 22.6274 (= "abs(-mountCircle / ( 2 * sqrt(2) ))")
  dimension "d849" distance P1 P2 = 22.6274 (= "abs(-mountCircle / ( 2 * sqrt(2) ))")
  dimension "d850" diameter C1 = 8.3138 (= "2 * ( nutAF ) / sqrt(3)")
extrude "Extrude39" cut sketch "B M4 Nut Pocket 3" profile of L1 L2 L3 L4 L5 L6 no distance stored
sketch "B M4 Nut Pocket 4" plane through (-0.3536, -0.3536, 0) normal (0.7071, 0.7071, 0) x axis (0, 0, 1)
  line L1 (24.7059, -19.0274) -> (26.7843, -22.6274)
  line L2 (20.549, -19.0274) -> (24.7059, -19.0274)
  line L3 (18.4705, -22.6274) -> (20.549, -19.0274)
  line L4 (20.549, -26.2274) -> (18.4705, -22.6274)
  line L5 (24.7059, -26.2274) -> (20.549, -26.2274)
  line L6 (26.7843, -22.6274) -> (24.7059, -26.2274)
  circle C1 centre (22.6274, -22.6274) radius 4.1569
  point P3 (26.7843, -22.6274)
  point P4 (24.7059, -19.0274)
  point P5 (20.549, -19.0274)
  point P6 (18.4705, -22.6274)
  point P7 (20.549, -26.2274)
  point P8 (24.7059, -26.2274)
  point P1 (0, 0)
  point P2 (22.6274, -22.6274)
  coincident C1 P3
  coincident C1 P4
  coincident C1 P5
  coincident C1 P6
  coincident C1 P7
  coincident C1 P8
  equal L1 L2
  equal L1 L3
  equal L1 L4
  equal L1 L5
  equal L1 L6
  horizontal L2
  dimension "d853" distance P1 P2 = 22.6274 (= "abs(mountCircle / ( 2 * sqrt(2) ))")
  dimension "d854" distance P1 P2 = 22.6274 (= "abs(-mountCircle / ( 2 * sqrt(2) ))")
  dimension "d855" diameter C1 = 8.3138 (= "2 * ( nutAF ) / sqrt(3)")
extrude "Extrude40" cut sketch "B M4 Nut Pocket 4" profile of L1 L2 L3 L4 L5 L6 no distance stored
sketch "B Hub Service Slots" plane through (0, 0, 0) normal (0, 0, 1) x axis (1, 0, 0)
  line L1 (-30.4056, -12.0208) -> (-14.8492, 3.5355)
  line L2 (-12.0208, -30.4056) -> (-30.4056, -12.0208)
  line L3 (3.5355, -14.8492) -> (-12.0208, -30.4056)
  line L4 (-14.8492, 3.5355) -> (3.5355, -14.8492)
  point P1 (0, 0)
  point P2 (-14.8492, 3.5355)
  point P3 (-30.4056, -12.0208)
  point P4 (-12.0208, -30.4056)
  point P5 (3.5355, -14.8492)
  dimension "d858" distance P1 P2 = 14.8492 (= "abs(( -8 mm - 13 mm ) / sqrt(2))")
  dimension "d859" distance P1 P2 = 3.5355 (= "abs(( -8 mm + 13 mm ) / sqrt(2))")
  dimension "d860" distance P1 P3 = 30.4056 (= "abs(( -30 mm - 13 mm ) / sqrt(2))")
  dimension "d861" distance P1 P3 = 12.0208 (= "abs(( -30 mm + 13 mm ) / sqrt(2))")
  dimension "d862" distance P1 P4 = 12.0208 (= "abs(( -30 mm + 13 mm ) / sqrt(2))")
  dimension "d863" distance P1 P4 = 30.4056 (= "abs(( -30 mm - 13 mm ) / sqrt(2))")
  dimension "d864" distance P1 P5 = 3.5355 (= "abs(( -8 mm + 13 mm ) / sqrt(2))")
  dimension "d865" distance P1 P5 = 14.8492 (= "abs(( -8 mm - 13 mm ) / sqrt(2))")
extrude "Extrude41" cut sketch "B Hub Service Slots" distance 76 (= "mountOD")
chamfer "Chamfer2" distance 0.3 (= "bedRelief")
chamfer "Chamfer3" distance 0.5 (= "tubeCornerChamfer")
chamfer "Chamfer4" sketch "A Facet 135 Triangle 1" distance 0.3 (= "tubeRimChamfer")
work_plane "WorkPlane25" RotateAngle 0 ExtraOffset 0
work_plane "WorkPlane26" AlongDistance 75 (= "bodyWidth / 2") ExtraOffset 0
sketch "A End Cord Port" plane through (0, 0, 75) normal (0, 0, 1) x axis (1, 0, 0)
  line L1 (125, 0) -> (0, 0)
  circle C1 centre (125, 0) radius 2.25
  point P1 (0, 0)
  point P2 (125, 0)
  horizontal L1
  dimension "d875" distance P1 P2 = 125 (= "abs(( 1 ) * ( ( 1 ) * cordStation ) + ( 0 ) * ( 0 mm ))")
  dimension "d876" diameter C1 = 4.5
extrude "Extrude40" cut sketch "A End Cord Port" profile of C1 no distance stored
chamfer "Chamfer5" distance 0.3 (= "bedRelief")
work_plane "WorkPlane27" RotateAngle 180 ExtraOffset 0
work_plane "WorkPlane28" AlongDistance 75 (= "bodyWidth / 2") ExtraOffset 0
sketch "A End Cord Port (1)" plane through (0, 0, -75) normal (0, 0, -1) x axis (-1, 0, 0)
  line L1 (-125, 0) -> (0, 0)
  circle C1 centre (-125, 0) radius 2.25
  point P1 (0, 0)
  point P2 (-125, 0)
  horizontal L1
  dimension "d884" distance P1 P2 = 125 (= "abs(( -1 ) * ( ( 1 ) * cordStation ) + ( 0 ) * ( 0 mm ))")
  dimension "d885" diameter C1 = 4.5
extrude "Extrude41" cut sketch "A End Cord Port (1)" profile of C1 no distance stored
chamfer "Chamfer6" distance 0.3 (= "bedRelief")
chamfer "Chamfer1" distance 0.3 (= "bedRelief")
chamfer "Chamfer2" distance 0.5 (= "tubeCornerChamfer")
chamfer "Chamfer3" sketch "A Facet 135 Triangle 1" distance 0.3 (= "tubeRimChamfer")
work_plane "WorkPlane21" RotateAngle 0 ExtraOffset 0
work_plane "WorkPlane22" AlongDistance 75 (= "bodyWidth / 2") ExtraOffset 0
sketch "B End Cord Port" plane through (0, 0, 75) normal (0, 0, 1) x axis (1, 0, 0)
  line L1 (-125, 0) -> (0, 0)
  circle C1 centre (-125, 0) radius 2.25
  point P1 (0, 0)
  point P2 (-125, 0)
  horizontal L1
  dimension "d896" distance P1 P2 = 125 (= "abs(( 1 ) * ( ( -1 ) * cordStation ) + ( 0 ) * ( 0 mm ))")
  dimension "d897" diameter C1 = 4.5
extrude "Extrude42" cut sketch "B End Cord Port" profile of C1 no distance stored
chamfer "Chamfer4" distance 0.3 (= "bedRelief")
work_plane "WorkPlane23" RotateAngle 180 ExtraOffset 0
work_plane "WorkPlane24" AlongDistance 75 (= "bodyWidth / 2") ExtraOffset 0
sketch "B End Cord Port (1)" plane through (0, 0, -75) normal (0, 0, -1) x axis (-1, 0, 0)
  line L1 (125, 0) -> (0, 0)
  circle C1 centre (125, 0) radius 2.25
  point P1 (0, 0)
  point P2 (125, 0)
  horizontal L1
  dimension "d905" distance P1 P2 = 125 (= "abs(( -1 ) * ( ( -1 ) * cordStation ) + ( 0 ) * ( 0 mm ))")
  dimension "d906" diameter C1 = 4.5
extrude "Extrude43" cut sketch "B End Cord Port (1)" profile of C1 no distance stored
chamfer "Chamfer5" distance 0.3 (= "bedRelief")
work_plane "WorkPlane1" AlongDistance 22.6 (= "qRearBase") ExtraOffset 0
sketch "D Rear Holder Blank sketch" plane through (15.9806, 15.9806, 0) normal (0.7071, 0.7071, 0) x axis (0, 0, 1)
  circle C1 centre (0, 0) radius 22
  dimension "d912" diameter C1 = 44 (= "coreOD")
extrude "Extrude1" new body sketch "D Rear Holder Blank sketch" along normal blind 10.2 (= "shoulder + rearSeatDepth")
work_plane "WorkPlane2" AlongDistance 22.6 (= "qRearBase") ExtraOffset 0
sketch "D Seal Relief sketch" plane through (15.9806, 15.9806, 0) normal (0.7071, 0.7071, 0) x axis (0, 0, 1)
  circle C1 centre (0, 0) radius 9.75
  dimension "d917" diameter C1 = 19.5 (= "raceRelief")
extrude "Extrude2" cut sketch "D Seal Relief sketch" along normal blind 10.2 (= "shoulder + rearSeatDepth")
work_plane "WorkPlane3" AlongDistance 25.6 (= "qRearBearing") ExtraOffset 0
sketch "D Rear Bearing Seat sketch" plane through (18.1019, 18.1019, 0) normal (0.7071, 0.7071, 0) x axis (0, 0, 1)
  circle C1 centre (0, 0) radius 11.1
  dimension "d922" diameter C1 = 22.2 (= "seatDiameter")
extrude "Extrude3" cut sketch "D Rear Bearing Seat sketch" along normal blind 7.2 (= "rearSeatDepth")
work_plane "WorkPlane4" AlongDistance 22.6 (= "qRearBase") ExtraOffset 0
sketch "D Support Bolt seed" plane through (15.9806, 15.9806, 0) normal (0.7071, 0.7071, 0) x axis (0, 0, 1)
  line L1 (17, 0) -> (0, 0)
  circle C1 centre (17, 0) radius 1.65
  point P1 (0, 0)
  point P2 (17, 0)
  horizontal L1
  dimension "d927" distance P1 P2 = 17 (= "supportCircle / 2")
  dimension "d928" diameter C1 = 3.3 (= "m3Clearance")
extrude "Extrude4" cut sketch "D Support Bolt seed" profile of C1 along normal blind 10.2 (= "shoulder + rearSeatDepth")
circular_pattern "C-Pattern1" TotalAngle 360
chamfer "Chamfer1" distance 0.4 (= "entryChamfer")
chamfer "Chamfer2" distance 0.3 (= "bedRelief")
work_plane "WorkPlane1" AlongDistance -2.5 (= "qFront - capThickness") ExtraOffset 0
sketch "C Front Bearing Cap Ring sketch" plane through (-1.7678, -1.7678, 0) normal (0.7071, 0.7071, 0) x axis (0, 0, 1)
  circle C1 centre (0, 0) radius 22
  circle C2 centre (0, 0) radius 9.75
  dimension "d937" diameter C1 = 44 (= "coreOD")
  dimension "d938" diameter C2 = 19.5 (= "raceRelief")
extrude "Extrude1" new body sketch "C Front Bearing Cap Ring sketch" along normal blind 3 (= "capThickness")
work_plane "WorkPlane2" AlongDistance -2.5 (= "qFront - capThickness") ExtraOffset 0
sketch "C Front Bearing Cap Bolt seed" plane through (-1.7678, -1.7678, 0) normal (0.7071, 0.7071, 0) x axis (0, 0, 1)
  line L1 (17, 0) -> (0, 0)
  circle C1 centre (17, 0) radius 1.65
  point P1 (0, 0)
  point P2 (17, 0)
  horizontal L1
  dimension "d943" distance P1 P2 = 17 (= "supportCircle / 2")
  dimension "d944" diameter C1 = 3.3 (= "m3Clearance")
extrude "Extrude2" cut sketch "C Front Bearing Cap Bolt seed" profile of C1 along normal blind 3 (= "capThickness")
circular_pattern "C-Pattern1" TotalAngle 360
chamfer "Chamfer1" distance 0.3 (= "bedRelief")
work_plane "WorkPlane1" AlongDistance 32.8 (= "qRearEnd") ExtraOffset 0
sketch "E Rear Bearing Cap Ring sketch" plane through (23.1931, 23.1931, 0) normal (0.7071, 0.7071, 0) x axis (0, 0, 1)
  circle C1 centre (0, 0) radius 22
  circle C2 centre (0, 0) radius 9.75
  dimension "d952" diameter C1 = 44 (= "coreOD")
  dimension "d953" diameter C2 = 19.5 (= "raceRelief")
extrude "Extrude1" new body sketch "E Rear Bearing Cap Ring sketch" along normal blind 3 (= "capThickness")
work_plane "WorkPlane2" AlongDistance 32.8 (= "qRearEnd") ExtraOffset 0
sketch "E Rear Bearing Cap Bolt seed" plane through (23.1931, 23.1931, 0) normal (0.7071, 0.7071, 0) x axis (0, 0, 1)
  line L1 (17, 0) -> (0, 0)
  circle C1 centre (17, 0) radius 1.65
  point P1 (0, 0)
  point P2 (17, 0)
  horizontal L1
  dimension "d958" distance P1 P2 = 17 (= "supportCircle / 2")
  dimension "d959" diameter C1 = 3.3 (= "m3Clearance")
